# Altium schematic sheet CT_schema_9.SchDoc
size 254 x 194 mm
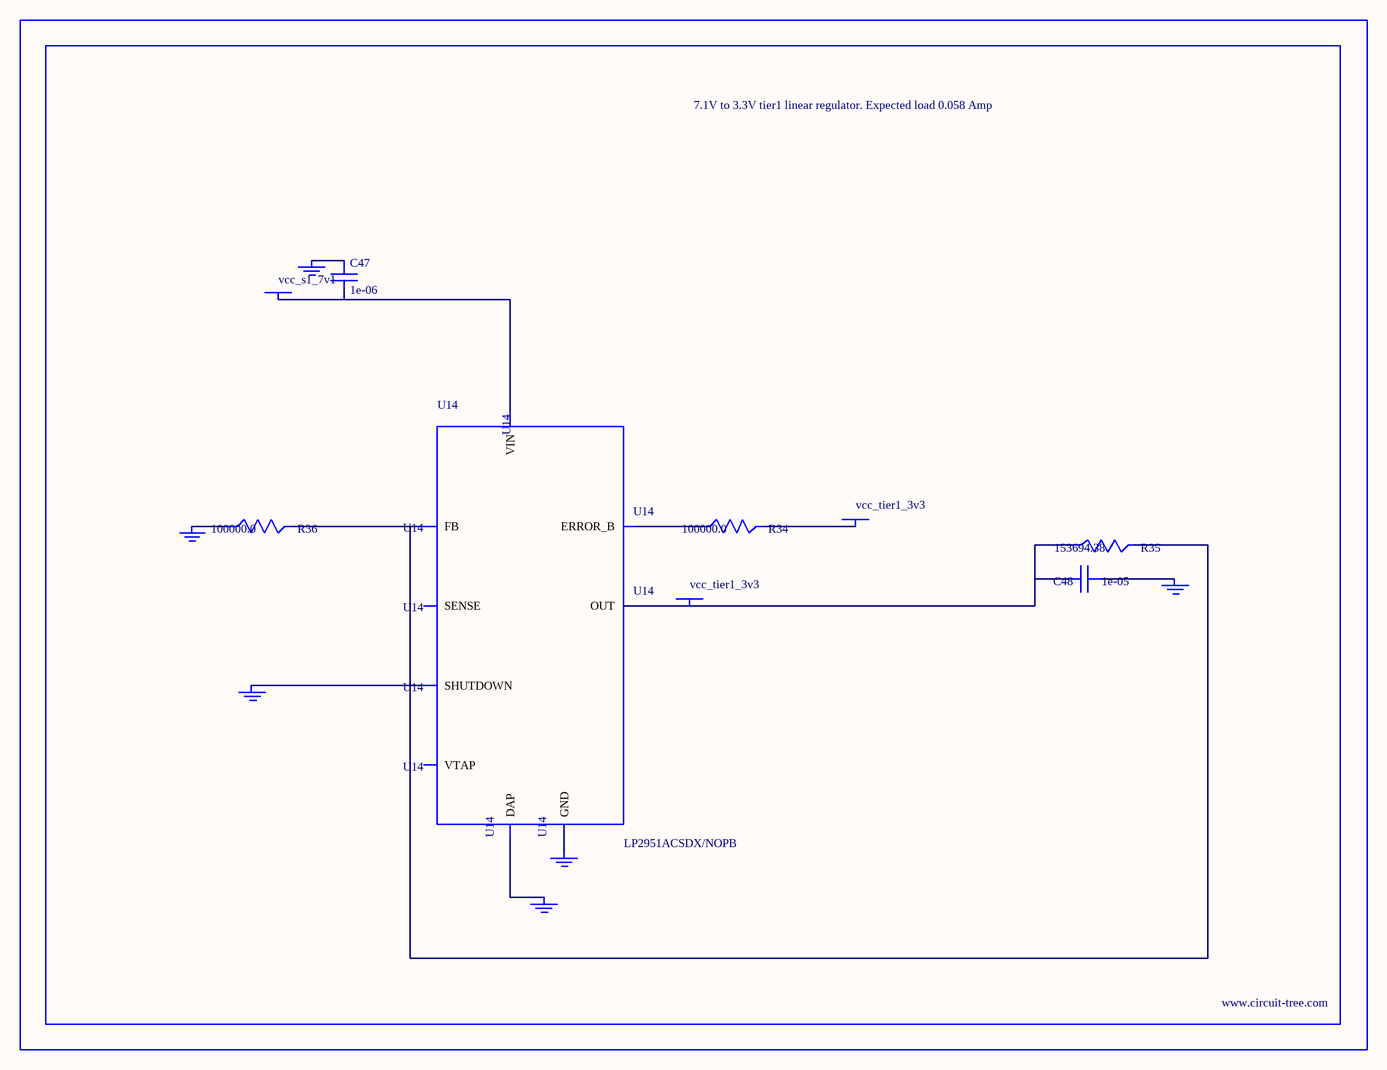
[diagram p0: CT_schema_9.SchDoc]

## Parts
BORDER8  (no value)
C47  1e-06  [C0603]
C48  1e-05  [C1210]
GND_INSTANCE_8_0  (no value)
GND_INSTANCE_8_1  (no value)
GND_INSTANCE_8_2  (no value)
GND_INSTANCE_8_3  (no value)
GND_INSTANCE_8_4  (no value)
GND_INSTANCE_8_5  (no value)
POWER_INSTANCE_8_0  vcc_tier1_3v3
POWER_INSTANCE_8_1  vcc_s1_7v1
POWER_INSTANCE_8_2  vcc_tier1_3v3
R34  100000.0  [R0603]
R35  153694.38  [R0603]
R36  100000.0  [R0603]
U14  LP2951ACSDX/NOPB  [WSON-8]

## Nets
NetC47_1: C47.1 GND_INSTANCE_8_3.0(GND)
NetC47_2: C47.2 POWER_INSTANCE_8_1.0(PWR) U14.8(VIN)
NetC48_1: C48.1 GND_INSTANCE_8_0.0(GND)
NetC48_2: C48.2 POWER_INSTANCE_8_2.0(PWR) R35.1 U14.1(OUT)
NetGND_INSTANCE_8_1_0: GND_INSTANCE_8_1.0(GND) U14.3(SHUTDOWN)
NetGND_INSTANCE_8_2_0: GND_INSTANCE_8_2.0(GND) R36.1
NetGND_INSTANCE_8_4_0: GND_INSTANCE_8_4.0(GND) U14.PAD(DAP)
NetGND_INSTANCE_8_5_0: GND_INSTANCE_8_5.0(GND) U14.4(GND)
NetPOWER_INSTANCE_8_0_0: POWER_INSTANCE_8_0.0(PWR) R34.2
NetR34_1: R34.1 U14.5(ERROR_B)
NetR35_2: R35.2 R36.2 U14.7(FB)

Not connected (* = marked no-connect by the designer): U14 2(SENSE) 6(VTAP)

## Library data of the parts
BORDER8 = BORDER_PAGE8
C47 = C0603C105K3RACTU
C48 = GRM32DR61E106MA12L
GND_INSTANCE_8_0-GND_INSTANCE_8_5 = GND
POWER_INSTANCE_8_0-POWER_INSTANCE_8_2 = PWR
R34 R36 = RC0603JR-07100KL
R35 = R35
